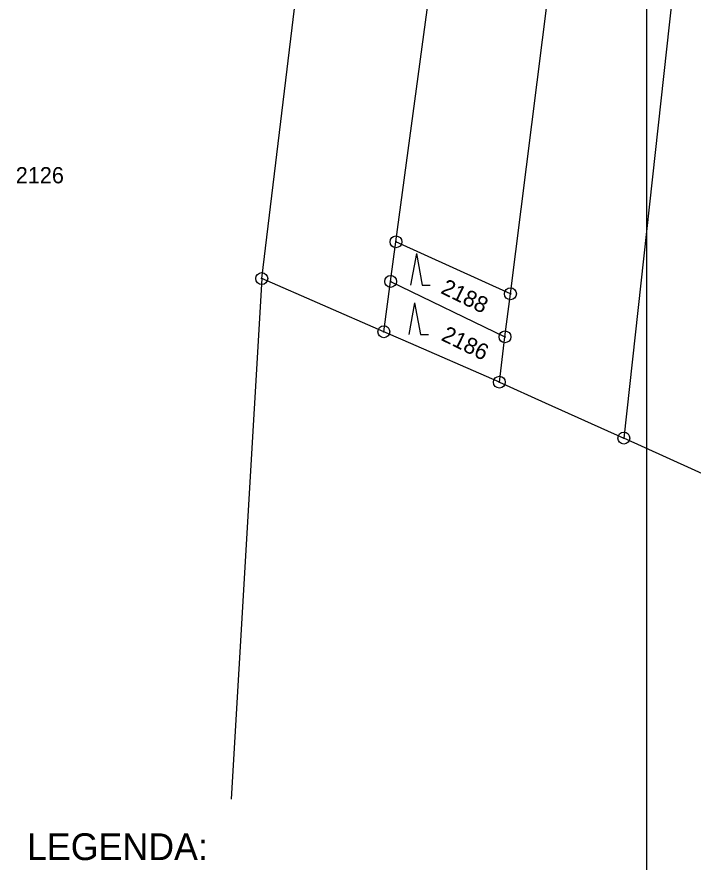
# Model space of a CAD drawing. Extents: x -566461 to -565198, y -1096301 to -1095707.
# Drawn here: x -565552.2 to -565495.3, y -1096010.8 to -1095939.7 of the extents above; entities that cross this region are included whole.
import ezdxf

# ---------------------------------------------------------------- set-up
doc = ezdxf.new("R2010")
doc.units = 0
for name, color, linetype in [('Vrstva 1', 7, 'Continuous'), ('Vrstva 18', 7, 'Continuous'), ('Vrstva 24', 7, 'Continuous'), ('Vrstva 25', 7, 'Continuous'), ('Vrstva 63', 7, 'Continuous')]:
    doc.layers.add(name, color=color, linetype=linetype)

msp = doc.modelspace()

# ---------------------------------------------------------------- linework, layer by layer
at = {"layer": 'Vrstva 1'}
for p, q in [((-565531.63, -1095961.73), (-565524.26, -1095900.94)), ((-565520.34, -1095958.64), (-565513.66, -1095908.86)), ((-565493.97, -1095909.58), (-565501.17, -1095975.14)), ((-565510.71, -1095963.01), (-565504.35, -1095912.44)), ((-565520.79, -1095961.97), (-565520.34, -1095958.64)), ((-565510.71, -1095963.01), (-565520.34, -1095958.64)), ((-565531.63, -1095961.73), (-565534.21, -1096005.513)), ((-565521.36, -1095966.2), (-565531.63, -1095961.73)), ((-565521.36, -1095966.2), (-565520.79, -1095961.97)), ((-565520.79, -1095961.97), (-565511.17, -1095966.63)), ((-565511.17, -1095966.63), (-565510.71, -1095963.01)), ((-565519.73, -1095966.91), (-565521.36, -1095966.2)), ((-565511.64, -1095970.44), (-565519.73, -1095966.91)), ((-565511.64, -1095970.44), (-565511.17, -1095966.63)), ((-565511.64, -1095970.44), (-565507.79, -1095972.17)), ((-565507.79, -1095972.17), (-565501.17, -1095975.14)), ((-565490.98, -1095979.78), (-565501.17, -1095975.14))]:
    msp.add_line(p, q, dxfattribs=at)
at = {"layer": 'Vrstva 24'}
for centre, radius in [((-565520.34, -1095958.64), 0.5), ((-565520.34, -1095958.64), 0.0327), ((-565531.63, -1095961.73), 0.5), ((-565520.79, -1095961.97), 0.5), ((-565531.63, -1095961.73), 0.0327), ((-565520.79, -1095961.97), 0.0327), ((-565510.71, -1095963.01), 0.5), ((-565510.71, -1095963.01), 0.0327), ((-565521.36, -1095966.2), 0.5), ((-565521.36, -1095966.2), 0.0327), ((-565511.17, -1095966.63), 0.5), ((-565511.17, -1095966.63), 0.0327), ((-565511.64, -1095970.44), 0.5), ((-565511.64, -1095970.44), 0.0327), ((-565501.17, -1095975.14), 0.5), ((-565501.17, -1095975.14), 0.0327)]:
    msp.add_circle(centre, radius, dxfattribs=at)
at = {"layer": 'Vrstva 25'}
for p, q in [((-565518.625, -1095959.613), (-565519.116, -1095962.293)), ((-565518.625, -1095959.613), (-565518.133, -1095962.293)), ((-565518.133, -1095962.293), (-565517.463, -1095962.293)), ((-565518.775, -1095963.763), (-565519.266, -1095966.443)), ((-565518.775, -1095963.763), (-565518.283, -1095966.443)), ((-565518.283, -1095966.443), (-565517.613, -1095966.443))]:
    msp.add_line(p, q, dxfattribs=at)
at = {"layer": 'Vrstva 63'}
msp.add_line((-565499.24, -1096150.73), (-565499.24, -1095853.73), dxfattribs=at)

# ---------------------------------------------------------------- texts
at = {"layer": 'Vrstva 1'}
msp.add_text('LEGENDA:', height=2.25, rotation=360, dxfattribs=at).set_placement((-565551.382, -1096010.624))
at = {"layer": 'Vrstva 18'}
msp.add_text('2126', height=1.36, dxfattribs=at).set_placement((-565552.324, -1095953.72))
for s, p in [('2188', (-565516.655, -1095962.92)), ('2186', (-565516.61, -1095966.877))]:
    msp.add_text(s, height=1.36, rotation=333.9, dxfattribs=at).set_placement(p)

doc.saveas('drawing.dxf')
